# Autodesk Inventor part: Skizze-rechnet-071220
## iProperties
Manager: Dr.-Ing. Roland Schröder
Company: Das Entwicklungsbuero
Created: 2007-12
Part Number: Skizze-rechnet-071220
Document SubType Name: Modeling
Catalog Web Link: www.Das-Entwicklungsbuero.de
Oberflaechen: Ra 6,3
Toleranzen: ISO 2768-m
Kanten: brechen
